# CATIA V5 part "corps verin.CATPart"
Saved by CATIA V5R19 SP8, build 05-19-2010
Part number: corps verin
Bounding box of the stored display mesh (mm): x -16 to -2, y 9.148 to 29, z 5.522 to 33.853
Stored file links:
  C:\Users\rcousturie\Desktop\EU_thinkMotion\iao\IAO_MMS_Groupe1\glenerrant\glenerrant\Nouveau dossier\corps verin.CATPart
  C:\Users\rcousturie\Desktop\EU_thinkMotion\iao\IAO_MMS_Groupe1\glenerrant\glenerrant\Nouveau dossier\squelette de base.CATPart
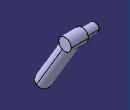
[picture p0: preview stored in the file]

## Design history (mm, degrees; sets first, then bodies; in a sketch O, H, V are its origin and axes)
Set1
  Point1: (0, 11, 6)
  Point2: (0, 26, 31)
  Plane1: type Offset, RefPlane yz-plane, Offset 10, reversed
  Plane2: type Normal, Curve Line1, RefPoint Point2
  Line1: stored without definition
Body1 (main body)
  Sketch1 on Plane1, origin (-10, 0, 0), H (0, 1, 0), V (0, 0, 1)
    circle A1 centre (26, 31) radius 3
    point P1 (26, 31)
    reference projected point E1 (26, 31) from Point2
    radius A1 = 3
    coincidence: P1 E1
  Pad1: profile Sketch1, direction (1, 0, 0), length 8
  Sketch2 on Plane2, origin (0, 20.5588, 34.2647), H (-1, 0, 0), V (0, -0.8575, 0.5145)
    circle A1 centre (6, -6.3454) radius 2
    point P1 (6, -6.3454)
    circle A2 centre (6, -6.3454) radius 3
    point P2 (6, -6.3454)
    reference projected point E1 (0, -6.3454) from Point2
    reference projected line E2 through (0, -6.3454) direction (-1, 0) from axis of face of Pad1 from Sketch1.A1
    radius A1 = 2
    radius A2 = 3
    distance P1 E1 = 6
    coincidence: P2 P1, P2 E2
  Pad2: profile Sketch2, direction (0, -0.5145, -0.8575), length 28
  Sketch3 on start face of Pad1, origin (-10, 0, 0), H (0, -1, 0), V (0, 0, 1)
    circle A1 centre (-26, 31) radius 2
    point P1 (-26, 31)
    reference projected point E1 (-26, 31) from Point2
    radius A1 = 2
    coincidence: P1 E1
  Pad3: profile Sketch3, direction (-1, 0, 0), length 6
